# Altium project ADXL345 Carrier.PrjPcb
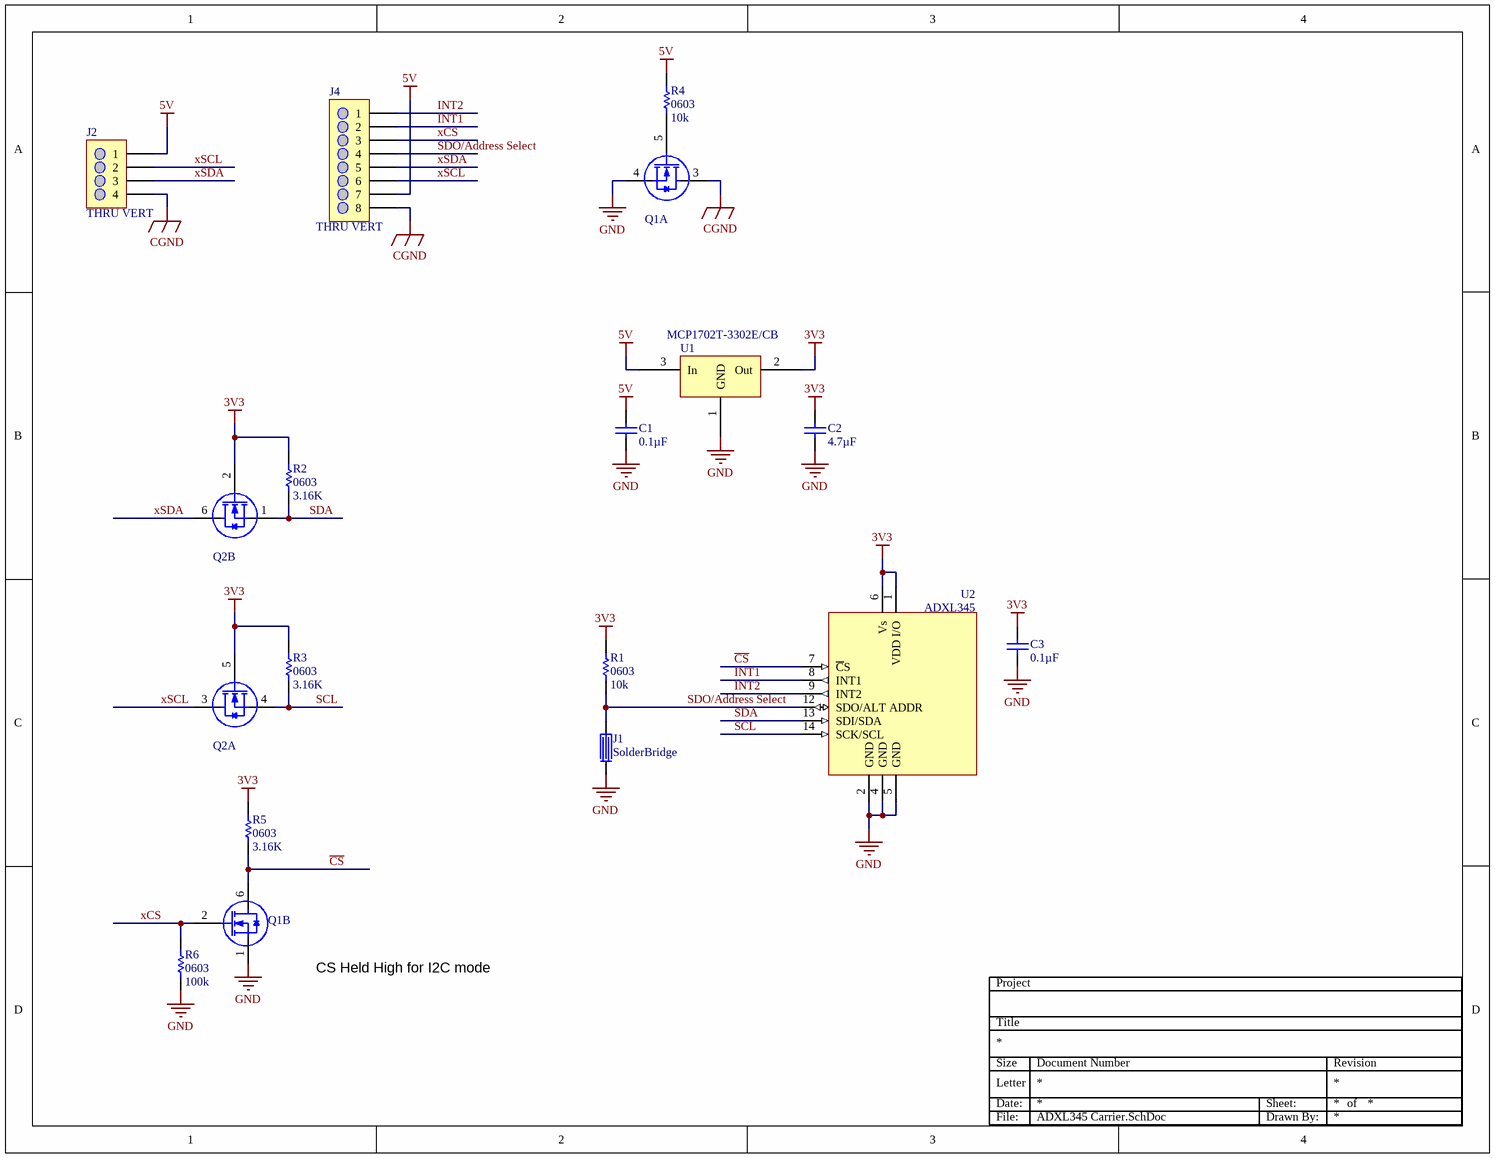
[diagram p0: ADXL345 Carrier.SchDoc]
2 sheets, 16 parts. Net scope: global (net labels, ports and power ports of the same name join across sheets).
Board file: ADXL345 Carrier.PcbDoc
Sheets:
  ADXL345 Carrier.SchDoc
  Title.SchDoc

## Sheet ADXL345 Carrier.SchDoc
size Letter

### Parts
C1  value 0.1µF  [C0805_C]  (hidden comment: 0.1uF 0805 Bypass)
C2  value 4.7µF  [C0805_C]  (hidden comment: 4.7uF 0805 25V X5R)
C3  value 0.1µF  [C0805_C]  (hidden comment: 0.1uF 0805 Bypass)
J1  SolderBridge  [Solder Bridge]  (no BOM)
J2  THRU VERT  [H100P4]
J4  THRU VERT  [H100P1x8]
Q1  FDG6303N - Dual N-Channel, Digital FET  [SC70-6]  (value not drawn)  (parts A,B of 2)
Q2  FDG6303N - Dual N-Channel, Digital FET  [SC70-6]  (value not drawn)  (parts A,B of 2)
R1  value 10k  Footprint: 0603  [R0603_C]  (hidden comment: 10k ohm 0603 1%)
R2  value 3.16K  Footprint: 0603  [R0603_C]  (hidden comment: 3.16k ohm 0603 1%)
R3  value 3.16K  Footprint: 0603  [R0603_C]  (hidden comment: 3.16k ohm 0603 1%)
R4  value 10k  Footprint: 0603  [R0603_C]  (hidden comment: 10k ohm 0603 1%)
R5  value 3.16K  Footprint: 0603  [R0603_C]  (hidden comment: 3.16k ohm 0603 1%)
R6  value 100k  Footprint: 0603  [R0603_C]  (hidden comment: 100k ohm 0603 1%)
U1  MCP1702T-3302E/CB  [SOT-23-3]
U2  ADXL345  [ADXL345]

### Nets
3V3: C2.1 C3.2 Q2.2(G) Q2.5(G) R1.2 R2.2 R3.2 R5.2 U1.2(Out) U2.1(VDD_I/O) U2.6(Vs)
5V: C1.2 J2.1 J4.7 R4.2 U1.3(In)
CGND: J2.4 J4.8 Q1.3(D)
GND: C1.1 C2.2 C3.1 J1.1 Q1.1(S) Q1.4(S) R6.1 U1.1(GND) U2.2(GND) U2.4(GND) U2.5(GND)
~{CS}: Q1.6(D) R5.1 U2.7(~{C}S)
INT1: J4.2 U2.8(INT1)
INT2: J4.1 U2.9(INT2)
SCL: Q2.4(S) R3.1 U2.14(SCK/SCL)
SDA: Q2.1(S) R2.1 U2.13(SDI/SDA)
SDO/Address Select: J1.2 J4.4 R1.1 U2.12(SDO/ALT_ADDR)
xCS: J4.3 Q1.2(G) R6.2
xSCL: J2.2 J4.6 Q2.3(D)
xSDA: J2.3 J4.5 Q2.6(D)
NetQ1_5: Q1.5(G) R4.1

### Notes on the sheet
- CS Held High for I2C mode

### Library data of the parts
C1 C3 = 0.1uF 0805 Bypass: MFG: Kemet; MFG_PN: C0805C104K5RACTU; DIST: DigiKey; DIST_PN: 399-1170-1-ND; Tolerance: ±10%; Temperature Coefficient: X7R; Voltage: 50; Checked: SCH 3/2/2008; Cost (1000): 0.01260
C2 = 4.7uF 0805 25V X5R: CERAMIC 4.7uF 25V X5R 0805; MFG: Panasonic - ECG; MFG_PN: ECJ-2FB1E475M; DIST: DigiKey; DIST_PN: PCC2321CT-ND; Tolerance: ±20%; Voltage: 25; Checked: SCH 3/2/2008; Cost (1000): 0.08988
J2 = H100 1x4 THRU VERT: 1x4 Bird Pins; DIST: Samtec; DIST_PN: TSW-104-07-T-S; Cost (1000): 0.125; Cost (MOQ): 0.147; BOM Note: Generic
J4 = H100 1x8 THRU VERT: 1x8 Bird Pins; DIST: Samtec; DIST_PN: TSW-108-07-T-S
Q1 Q2 = FDG6303N - Dual N-Channel, Digital FET: 25V Dual N Channel Signal MOSFETS; MFG: Fairchild Semiconductor; DIST: DIGIKEY; DIST_PN: FDG6303NCT-ND; I_D Continuous: 500mA; R?JC: 415 C/W; R_DS: 0.60 Ohms; Topology: 2 N; V_DS: 25; V_GS: 8 V; Cost (1000): 0.09120; Cost (MOQ): 0.38000; Q_G (nC): 0.29; V_THRESH (Volts): 0.65 - 0.80 - 1.50
R1 R4 = 10k ohm 0603 1%: MFG: Rohm; MFG_PN: MCR03EZPFX1002; DIST: DigiKey; DIST_PN: RHM10.0KHCT-ND; Power: 0.1; Cost (1000): 0.01595; Cost (MOQ): 0.076; BOM Note: Generic - May be replaced by equal or better part
R2 R3 R5 = 3.16k ohm 0603 1%: MFG: Rohm; MFG_PN: MCR03EZPFX3161; DIST: DigiKey; DIST_PN: RHM3.16KHCT-ND; Power: 0.1 W; Cost (1000): 0.01595; Cost (MOQ): 0.089
R6 = 100k ohm 0603 1%: MFG: Rohm; MFG_PN: MCR03EZPFX1003; DIST: DigiKey; DIST_PN: RHM100KHCT-ND; Power: 0.1; Cost (1000): 0.01595; Cost (MOQ): 0.076; BOM Note: Generic - May be replaced by equal or better part
U1 = MCP1702T-3302E/CB: IC REG LDO 200MA 3.3V SOT-23A; DIST: DigiKey; MFG: Microchip; Voltage Output: 3.3; Topology: Linear, Fixed; Max Voltage: 13.2; Cost (1000): 0.36000; Cost (MOQ): 0.59000
U2 = ADXL345: Small, Low Power, 3-Axis +/-3g iMEMS Accelerometer; MFG: Analog Devices

## Sheet Title.SchDoc
size Letter; SheetNumber: 1
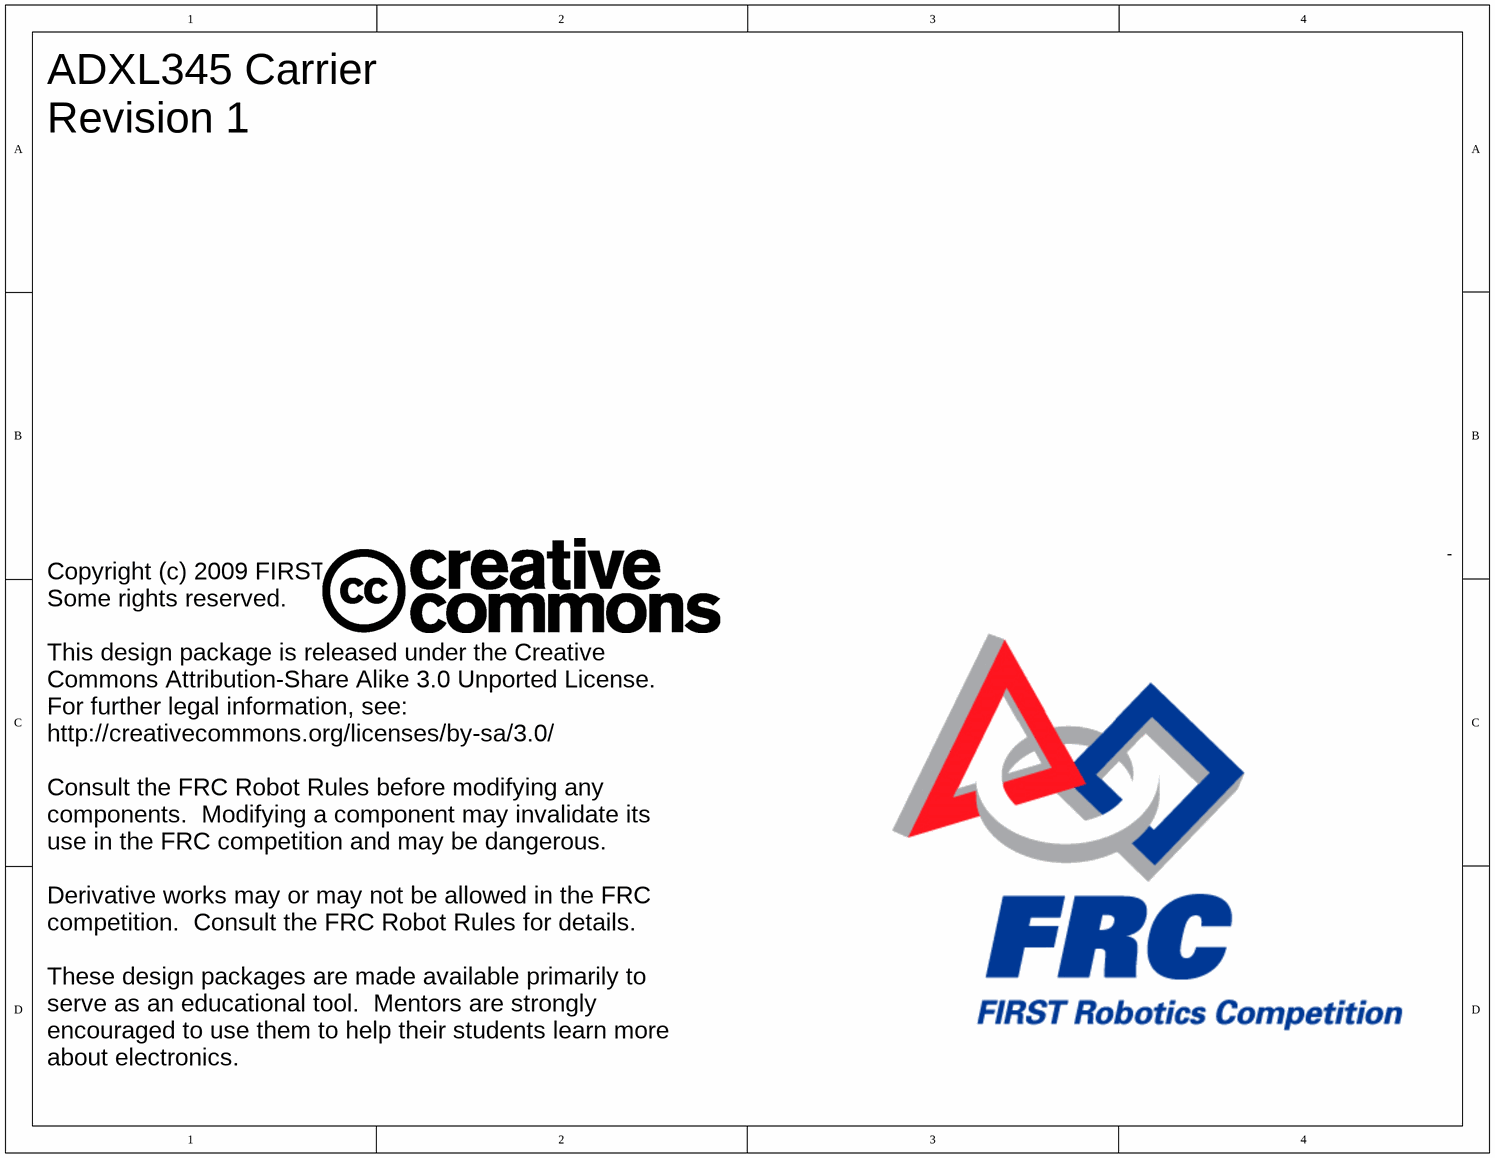
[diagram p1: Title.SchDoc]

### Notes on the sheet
- ADXL345 Carrier
  Revision 1
- Copyright (c) 2009 FIRST
  Some rights reserved.
  This design package is released under the Creative Commons Attribution-Share Alike 3.0 Unported License.  For further legal information, see:
  http://creativecommons.org/licenses/by-sa/3.0/
  Consult the FRC Robot Rules before modifying any components.  Modifying a component may invalidate its use in the FRC competition and may be dangerous.
  Derivative works may or may not be allowed in the FRC competition.  Consult the FRC Robot Rules for details.
  These design packages are made available primarily to serve as an educational tool.  Mentors are strongly encouraged to use them to help their students learn more about electronics.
